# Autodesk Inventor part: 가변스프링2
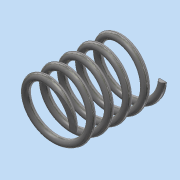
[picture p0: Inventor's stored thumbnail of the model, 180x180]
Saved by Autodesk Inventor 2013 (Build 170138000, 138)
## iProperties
Created: 2018-10
Part Number: 가변스프링2
Material: 스테인리스강
Document SubType Name: Modeling
Designer: Administrator
Density: 8.08 g/cm^3
Mass: 6.28353 g
Surface Area: 15.7652 cm^2
Volume: 0.777664 cm^3
Author: Administrator
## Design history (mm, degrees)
sketch "스케치1"
  geometry: L1 (0, 0)-(0, 25.765); L2 (0, 0)-(8, 0); L3 (0, 25.765)-(8, 25.765); C1 r 1 at (8, 0)
  constraints: 6 end point, 1 centre point, 1 horizontal alignment, 1 parallel, 1 perpendicular, 1 vertical
  dimensions: "d0" = 25.76498 distance of L1.start L1.end (derived); "d1" = 2 diameter of C1; "d2" = 16 diameter of L2.end L1; "d3" = 8 distance of L1.end L3.end
feature "코일1" sketch "스케치1" pitch "d4" = 10; turns "d6" = 5; dims "d5" = 25.76498 (= d0), "d7" = 0, angle "d8" = 90 deg, angle "d9" = 90 deg, "d10" = 0, "d11" = 0
sketch "스케치2"
  geometry: L1 (25.765, 10)-(0, 10); L2 (0, 10)-(0, -10); L3 (0, -10)-(25.765, -10); L4 (25.765, -10)-(25.765, 10); 2 further points
  constraints: 8 end point, 2 parallel, 1 coincident, 1 horizontal, 1 midpoint, 1 perpendicular
  dimensions: "d12" = 20 distance of L1.end L2.end; "d14" = 25.76498 distance of L2.end L3.end (derived)
extrude "돌출1" sketch "스케치2" stored distance "d15" = 0; taper "d16" = 0 deg
node "솔리드1"
